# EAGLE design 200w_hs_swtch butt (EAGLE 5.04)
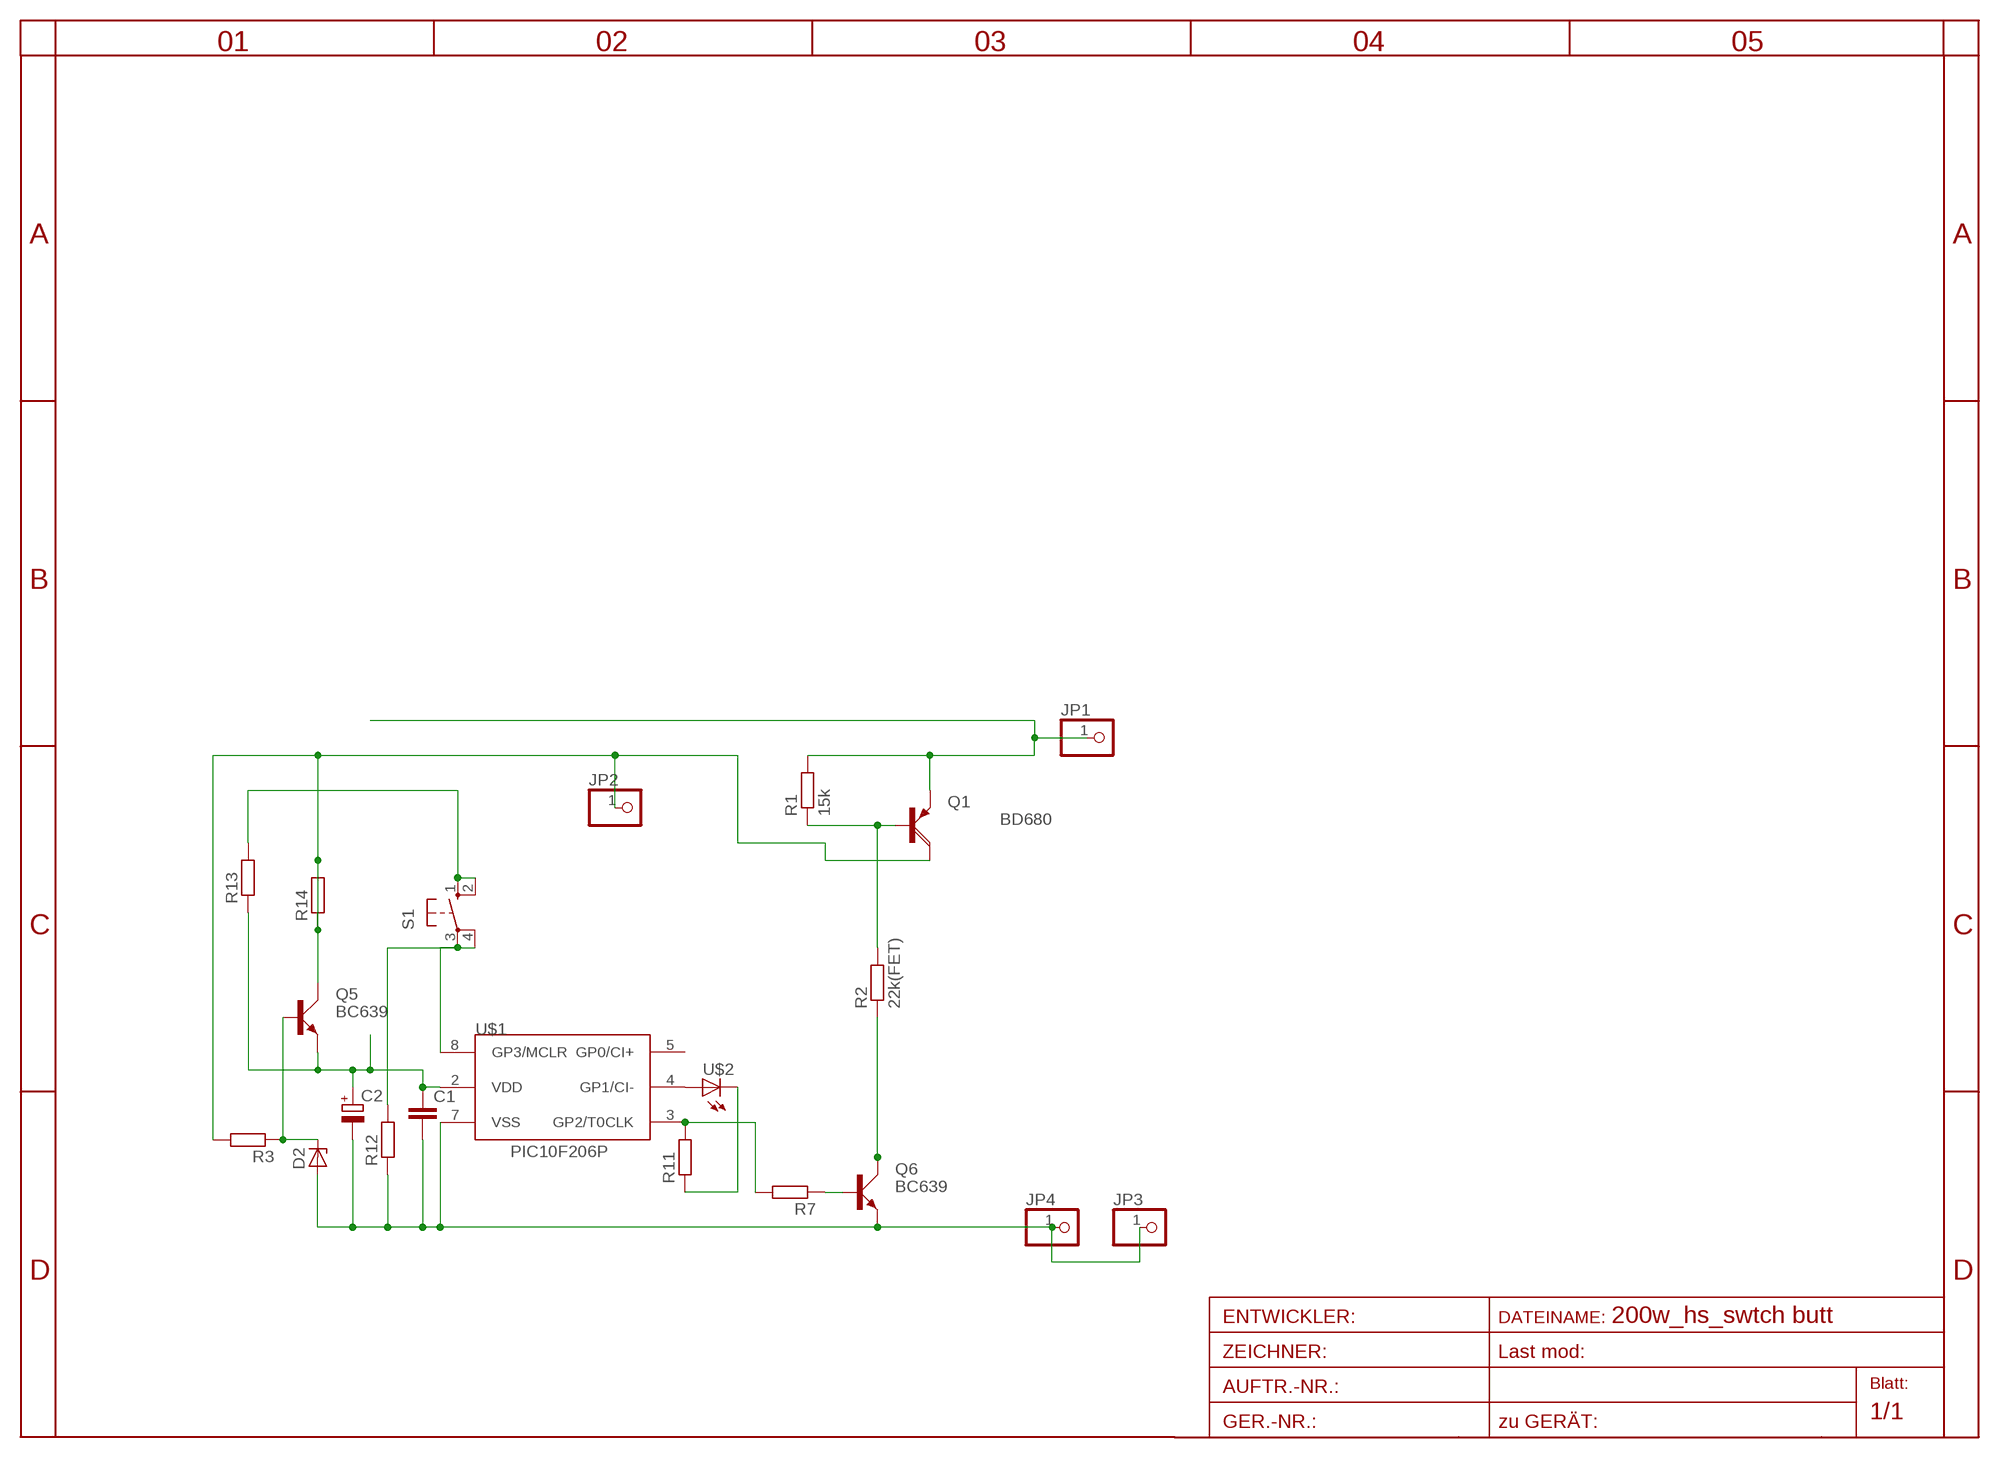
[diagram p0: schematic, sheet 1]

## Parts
C1  C-EU050-030X075  [C050-030X075]
C2  CPOL-EUE2.5-5  [E2,5-5]
D2  ZENER-DIODEZD-7.5  [ZDIO-7.5]
JP1  PINHD-1X1  [1X01]
JP2  PINHD-1X1  [1X01]
JP3  PINHD-1X1  [1X01]
JP4  PINHD-1X1  [1X01]
Q1  BD680  [TO126AV]
Q5  BC639  [SOT54D]
Q6  BC639  [SOT54D]
R1  15k  R-EU_0207/10  [0207/10]
R2  22k(FET)  R-EU_0207/10  [0207/10]
R3  R-EU_0207/10  [0207/10]
R7  R-EU_0207/10  [0207/10]
R11  R-EU_0207/10  [0207/10]
R12  R-EU_0207/10  [0207/10]
R13  R-EU_0207/10  [0207/10]
R14  R-EU_0207/10  [0207/10]
S1  10-XX  [B3F-10XX]
U$1  PIC10F206P  [DIL8]
U$2  LED3MM  [LED3MM]

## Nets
GND: C1.2 C2.- D2.A JP3.1 JP4.1 Q6.E R12.1 U$1.7(VSS)
N$2: C1.1 C2.+ Q5.E R13.1 U$1.2(VDD)
N$5: U$1.4(GP1/CI-) U$2.A
N$6: R11.1 U$2.K(C)
N$9: R7.2 R11.2 U$1.3(GP2/T0CLK)
N$10: Q6.B R7.1
N$11: R12.2 S1.3(P) S1.4(P1) U$1.8(GP3/MCLR)
N$12: Q6.C R2.1
N$13: Q1.B R1.1 R2.2
N$15: R13.2 S1.1(S) S1.2(S1)
N$16: D2.C Q5.B R3.1
V+IN: JP1.1 Q1.E R1.2
V+OUT: JP2.1 Q1.C Q5.C R3.2 R14.1 R14.2
Unconnected: U$1.5(GP0/CI+)

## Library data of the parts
C1 = rcl:C-EU: CAPACITOR, European symbol
C2 = rcl:CPOL-EU: POLARIZED CAPACITOR, European symbol
D2 = diode-1:ZENER-DIODE: Z-Diode
JP1-JP4 = pinhead:PINHD-1X1: PIN HEADER
Q1 = transistor-power:BD680: PNP DARLINGTON TRANSISTOR
Q5 Q6 = transistor-small-signal:BC639: NPN TRANSISTOR
R1-R3 R7 R11-R14 = rcl:R-EU_: RESISTOR, European symbol
S1 = switch-omron:10-XX: OMRON SWITCH
U$1 = microchip-5:PIC10F2*: uPC nW 0,25/0,5k Program Flash memory Comparator
U$2 = led(2):LED: LED

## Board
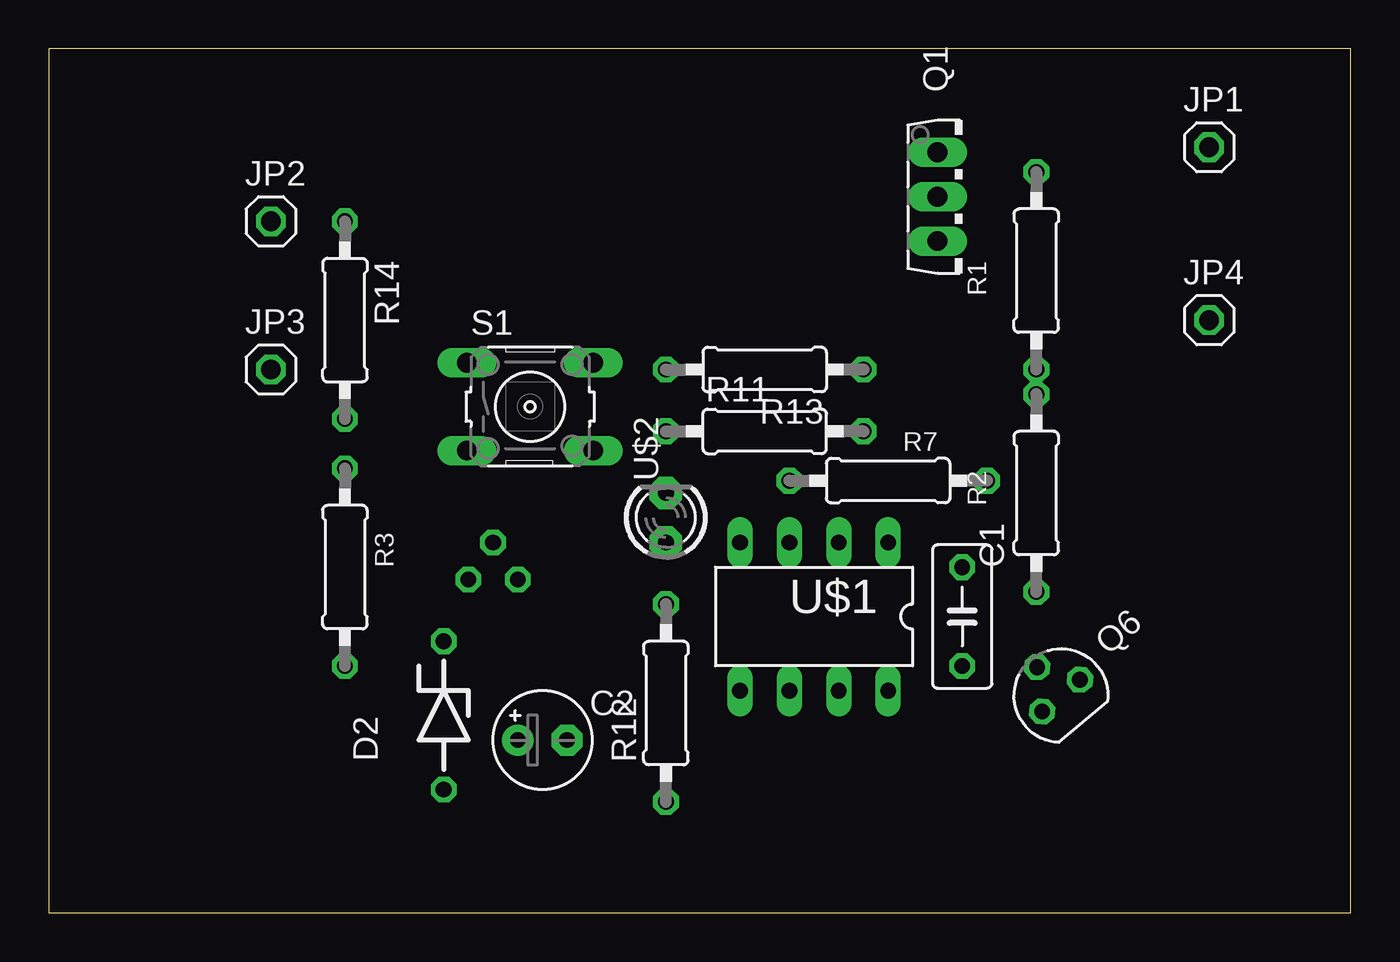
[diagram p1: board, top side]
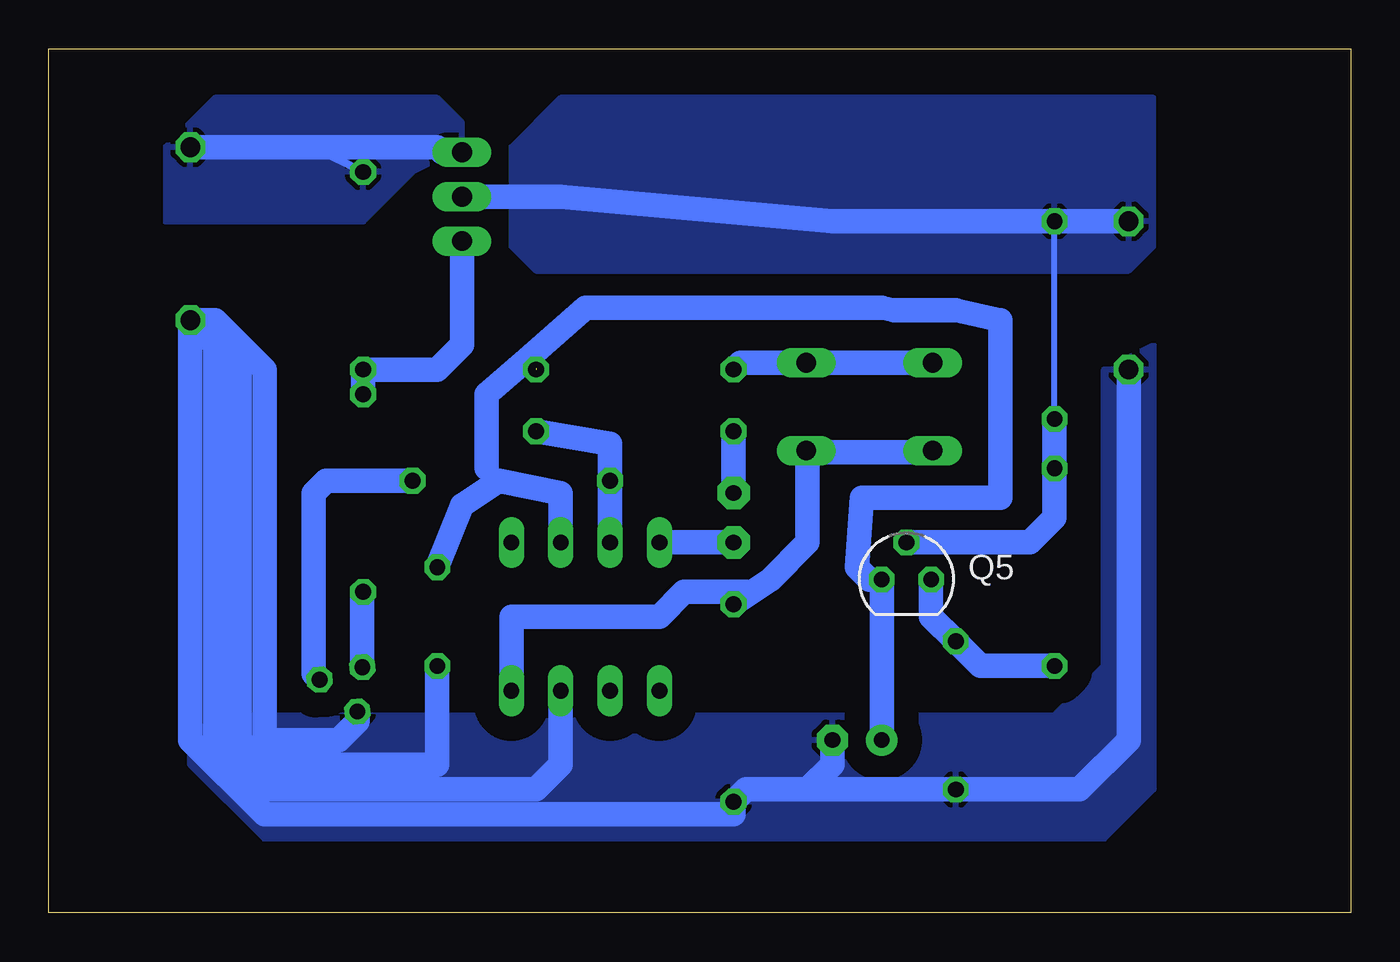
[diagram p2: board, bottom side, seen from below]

Size 66.98 x 44.44 mm. Coordinates in mm from the lower left corner, seen from the top.
Outline: 0,0 66.98,0 66.98,44.44 0,44.44 0,0
Copper layers (1*16): Top 0.035mm / dielectric 1.5mm / Bottom 0.035mm
Design rules "default": minimum track width 10mil, minimum drill 24mil, track to track 8mil, track to pad 8mil, pad to pad 8mil, via to via 8mil, smd to smd 8mil, copper to edge 40mil, drill to drill 8mil, minimum pad ring 10mil, minimum via ring 8mil, stop-mask expansion 4mil, vias tented up to drill 0mil, thermal gap 10mil

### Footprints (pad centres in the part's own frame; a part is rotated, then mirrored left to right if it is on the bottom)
C050-030X075 = drill 0.813 octagon: 1 -2.54,0; 2 2.54,0
E2,5-5 = drill 0.813 pad 1.6 round: + -1.27,0 | drill 0.813 pad 1.6 octagon: - 1.27,0
ZDIO-7.5 = drill 0.813 octagon: A 3.81,0; C -3.81,0
1X01 = drill 1.016 octagon: 1 0,0
TO126AV = drill 1.016 long: B 2.286,-1.27; C 0,-1.27; E -2.286,-1.27
SOT54D = drill 0.813 octagon: B 1.27,0; C 0,1.905; E -1.27,0
0207/10 = drill 0.813 octagon: 1 -5.08,0; 2 5.08,0
B3F-10XX = drill 1.016 long: 1 -3.251,2.261; 2 3.251,2.261; 3 -3.251,-2.261; 4 3.251,-2.261
DIL8 = drill 0.813 long: 1 -3.81,-3.81; 2 -1.27,-3.81; 3 1.27,-3.81; 4 3.81,-3.81; 5 3.81,3.81; 6 1.27,3.81; 7 -1.27,3.81; 8 -3.81,3.81
LED3MM = drill 0.813 pad 1.676 octagon: A -1.27,0; K 1.27,0

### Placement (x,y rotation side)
C1  46.99,15.24 270 top
C2  25.4,8.89 0 top
D2  20.32,10.16 270 top
JP1  59.69,39.37 0 top
JP2  11.43,35.56 0 top
JP3  11.43,27.94 0 top
JP4  59.69,30.48 0 top
Q1  46.99,36.83 270 top
Q5  22.86,17.14 0 bottom
Q6  52.07,11.18 40 top
R1  50.8,33.02 90 top
R2  50.8,21.59 90 top
R3  15.24,17.78 90 top
R7  43.18,22.23 180 top
R11  36.83,24.77 0 top
R12  31.75,10.79 90 top
R13  36.83,27.94 180 top
R14  15.24,30.48 270 top
S1  24.77,26.04 0 top
U$1  39.37,15.24 180 top
U$2  31.75,20.32 90 top

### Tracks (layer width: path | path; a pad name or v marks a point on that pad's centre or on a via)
GND
  Bottom 1.27: JP4.1 59.69,8.89 55.88,5.08 31.75,5.08 R12.1 31.11,6.35 27.94,6.35 | JP3.1 11.43,8.89 13.97,6.35 D2.A 27.94,6.35 | C2.- 26.67,7.62 27.94,6.35 | U$1.7 40.64,7.62 41.91,6.35 55.88,6.35 58.42,8.89 58.42,29.21 59.05,29.84 | JP4.1 59.05,29.84 | C1.2 46.99,7.62 55.88,7.62 57.15,8.89 57.15,27.94 59.05,29.84 | Q6.E 51.1,9.86 52.07,8.89 55.88,8.89 55.88,27.94 58.42,30.48 JP4.1
  pour Bottom (isolate 1.27): 10.16,29.21 10.16,6.35 12.7,3.81 55.88,3.81 59.69,7.62 59.69,8.89 58.42,10.16 15.24,10.16 12.7,12.7 12.7,27.94
N$2  (1 unrouted)
  Bottom 0.406: 44.45,22.86 43.81,22.23
  Bottom 1.27: 42.38,28.48 39.37,31.11 24.13,31.11 23.5,30.99 20.32,30.99 18.03,30.48 18.03,21.34 25.15,21.34 25.4,17.78 24.77,17.14 Q5.E C2.+ | 42.38,28.48 44.45,26.67 44.45,22.86 | U$1.2 40.64,21.59 43.81,22.23 45.72,20.95 C1.1 | 42.38,28.48 41.91,28.01
N$5
  Bottom 1.27: U$2.A U$1.4
N$6
  Bottom 1.27: U$2.K R11.1
N$9
  Bottom 1.27: U$1.3 R7.2 38.1,24.13 R11.2
N$10
  Bottom 1.27: R7.1 52.7,22.23 53.34,21.59 53.34,12.29 Q6.B
N$11
  Bottom 1.27: 27.94,23.7 27.94,19.05 29.84,17.14 R12.2 31.11,16.51 34.29,16.51 35.56,15.24 43.18,15.24 U$1.8 | 27.94,23.7 S1.4 | 27.94,23.7 21.59,23.7 S1.3
N$12
  Bottom 1.27: Q6.C 50.84,16.46 R2.1
N$13
  Bottom 1.27: Q1.B 45.72,29.21 46.99,27.94 R1.1 R2.2
N$15
  Bottom 1.27: S1.1 S1.2 31.39,28.3 R13.2
N$16
  Bottom 1.27: R3.1 19.05,12.7 D2.C 21.59,15.24 Q5.B
V+IN
  Bottom 0.406: 53.34,39.37 R1.2
  Bottom 1.27: JP1.1 53.34,39.37 46.99,39.37 46.74,39.12 Q1.E
  pour Bottom: 45.72,39.37 45.72,40.64 46.99,41.91 58.42,41.91 60.96,39.37 60.96,35.56 50.8,35.56 48.26,38.1
V+OUT
  Bottom 0.305: R14.2 R14.1
  Bottom 1.27: Q1.C 40.64,36.83 26.67,35.56 17.78,35.56 R14.1 JP2.1 | Q5.C 16.51,19.05 15.24,20.32 R3.2 R14.2
  pour Bottom: 10.16,41.91 40.64,41.91 43.18,39.37 43.18,36.83 43.18,34.29 41.91,33.02 11.43,33.02 10.16,34.29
